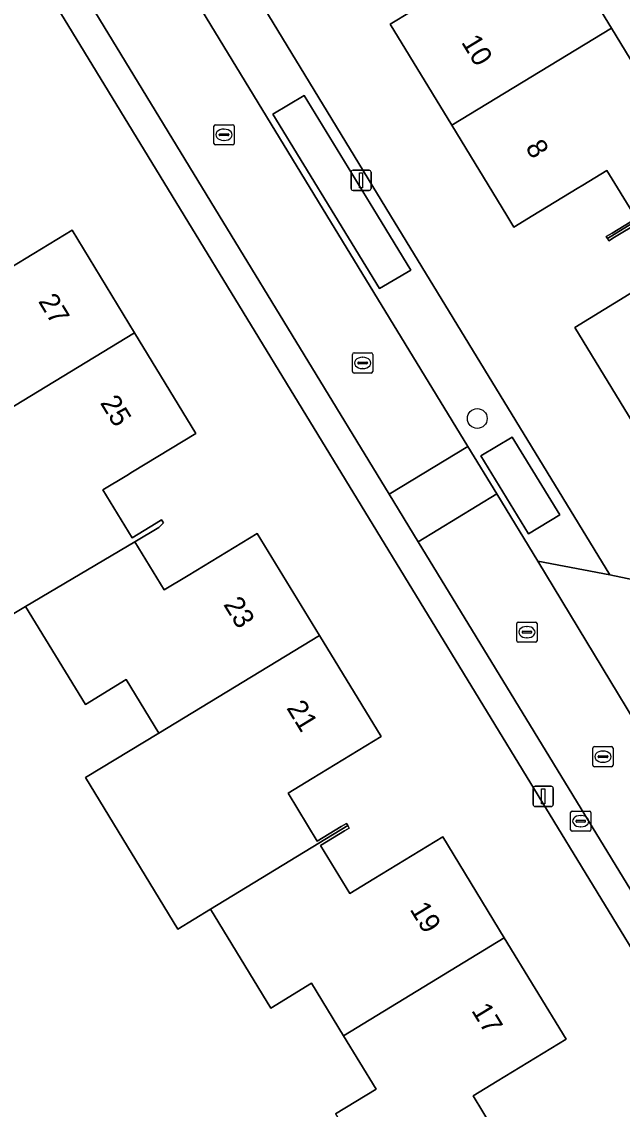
# Model space of a CAD drawing. Extents: x 157767 to 159172, y 387839 to 389425.
# Drawn here: x 158106.2 to 158135.9, y 388455.8 to 388509.6 of the extents above; entities that cross this region are included whole.
import ezdxf

# ---------------------------------------------------------------- set-up
doc = ezdxf.new("R2010")
doc.units = 0
for name, color, linetype in [('IMGEO_Boom', 7, 'Continuous'), ('IMGEO_Brandkraan', 7, 'Continuous'), ('IMGEO_Erf', 7, 'Continuous'), ('IMGEO_Kolk', 7, 'Continuous'), ('IMGEO_Lichtmast', 7, 'Continuous'), ('IMGEO_Pand', 7, 'Continuous'), ('IMGEO_Pand_nummerreeks', 7, 'Continuous'), ('IMGEO_Parkeervlak_open', 7, 'Continuous'), ('IMGEO_Rijbaan_lokaal_open', 7, 'Continuous'), ('IMGEO_Rioolput', 7, 'Continuous'), ('IMGEO_Voetpad_open', 7, 'Continuous')]:
    doc.layers.add(name, color=color, linetype=linetype)

msp = doc.modelspace()

# ---------------------------------------------------------------- linework, layer by layer
at = {"layer": 'IMGEO_Boom'}
msp.add_circle((158128.743, 388489.955), 0.489, dxfattribs=at)
at = {"layer": 'IMGEO_Brandkraan'}
for p, q in [((158133.361, 388469.598), (158133.361, 388470.45)), ((158133.436, 388470.524), (158134.288, 388470.524)), ((158133.62, 388470.018), (158133.62, 388470.03)), ((158133.663, 388470.067), (158134.061, 388470.067)), ((158133.849, 388470.304), (158133.874, 388470.304)), ((158134.104, 388470.03), (158134.104, 388470.018)), ((158134.362, 388470.45), (158134.362, 388469.598)), ((158134.288, 388469.524), (158133.436, 388469.524)), ((158134.058, 388469.981), (158133.66, 388469.981)), ((158133.872, 388469.744), (158133.847, 388469.744))]:
    msp.add_line(p, q, dxfattribs=at)
for points in [[(158133.361, 388469.598), (158133.361, 388470.45)], [(158133.436, 388470.524), (158134.288, 388470.524)], [(158134.362, 388470.45), (158134.362, 388469.598)], [(158134.288, 388469.524), (158133.436, 388469.524)]]:
    msp.add_lwpolyline(points, dxfattribs=at)
for centre, radius, start, end in [((158133.438, 388470.448), 0.0765, 91.552, 178.448), ((158133.438, 388470.448), 0.0765, 91.552, 178.448), ((158133.66, 388470.027), 0.0403, 85.8775, 175.7526), ((158134.065, 388470.029), 0.0386, 1.7309, 96.639), ((158134.286, 388470.448), 0.0765, 1.552, 88.448), ((158134.286, 388470.448), 0.0765, 1.552, 88.448), ((158133.438, 388469.6), 0.0765, 181.552, 268.448), ((158133.438, 388469.6), 0.0765, 181.552, 268.448), ((158133.657, 388470.017), 0.0366, 178.938, 274.7102), ((158134.061, 388470.024), 0.043, 264.8664, 352.4533), ((158134.286, 388469.6), 0.0765, 271.552, 358.448), ((158134.286, 388469.6), 0.0765, 271.552, 358.448)]:
    msp.add_arc(centre, radius, start, end, dxfattribs=at)
for centre, major_axis, ratio, start_param, end_param in [((158133.848, 388470.024), (-0.387, 0.002), 0.722429, 4.712389, 7.853982), ((158133.873, 388470.024), (-0.39, 0.002), 0.717154, 1.570796, 4.712389)]:
    msp.add_ellipse(centre, major_axis=major_axis, ratio=ratio, start_param=start_param, end_param=end_param, dxfattribs=at)
at = {"layer": 'IMGEO_Erf'}
for points in [[(158114.935, 388440.198), (158118.209, 388434.304), (158121.651, 388436.4), (158122.951, 388434.264), (158119.424, 388432.116), (158121.853, 388427.742), (158122.495, 388426.586), (158149.258, 388442.588), (158114.242, 388500), (158071.868, 388569.477)], [(158091.923, 388553.434), (158124.459, 388500), (158135.292, 388482.21), (158138.896, 388481.458), (158169.322, 388500), (158184.058, 388508.98), (158185.047, 388512.009)], [(158133.795, 388511.879), (158135.376, 388509.282), (158136.994, 388506.624)], [(158136.515, 388500), (158135.156, 388502.231), (158133.966, 388501.506), (158133.679, 388501.331), (158131.493, 388500), (158130.552, 388499.427), (158130.203, 388500), (158127.478, 388504.475), (158124.43, 388509.481), (158127.546, 388511.378)], [(158136.723, 388499.647), (158135.538, 388498.925), (158135.251, 388498.75), (158135.178, 388498.87), (158135.125, 388498.957), (158135.413, 388499.132), (158136.602, 388499.857)], [(158105.289, 388497.191), (158108.705, 388499.27), (158111.791, 388494.202), (158114.824, 388489.221), (158111.685, 388487.311), (158111.408, 388487.142), (158110.22, 388486.419), (158111.666, 388484.045), (158112.861, 388484.772), (158113.131, 388484.936), (158113.216, 388484.798), (158112.992, 388484.56), (158111.804, 388483.855), (158113.257, 388481.467), (158114.445, 388482.19), (158117.861, 388484.269), (158120.933, 388479.223), (158123.986, 388474.21), (158120.57, 388472.13), (158119.383, 388471.407), (158120.83, 388469.033), (158122.017, 388469.756), (158122.273, 388469.912), (158122.337, 388469.806), (158122.412, 388469.683), (158122.178, 388469.54), (158120.99, 388468.817), (158122.436, 388466.442), (158123.624, 388467.166), (158127.039, 388469.246), (158130.081, 388464.25), (158133.138, 388459.229), (158129.722, 388457.149), (158128.535, 388456.426), (158129.981, 388454.052)], [(158136.631, 388489.432), (158133.565, 388494.467), (158136.982, 388496.549)], [(158121.732, 388455.537), (158123.737, 388456.758), (158122.126, 388459.404), (158120.544, 388462.002), (158118.527, 388460.774), (158115.546, 388465.67), (158113.932, 388464.687), (158109.368, 388472.181), (158112.994, 388474.389), (158111.385, 388477.031), (158109.358, 388475.796), (158106.404, 388480.648), (158105.408, 388480.057)]]:
    msp.add_lwpolyline(points, dxfattribs=at)
at = {"layer": 'IMGEO_Kolk'}
for p, q in [((158115.79, 388504.498), (158116.642, 388504.498)), ((158115.715, 388503.572), (158115.715, 388504.424)), ((158115.974, 388503.992), (158115.974, 388504.004)), ((158116.412, 388503.955), (158116.014, 388503.955)), ((158116.017, 388504.041), (158116.415, 388504.041)), ((158116.203, 388504.278), (158116.228, 388504.278)), ((158116.458, 388504.004), (158116.458, 388503.992)), ((158116.716, 388504.424), (158116.716, 388503.572)), ((158116.642, 388503.498), (158115.79, 388503.498)), ((158116.226, 388503.718), (158116.201, 388503.718)), ((158122.648, 388493.204), (158123.5, 388493.204)), ((158122.573, 388492.278), (158122.573, 388493.13)), ((158122.832, 388492.698), (158122.832, 388492.71)), ((158123.27, 388492.661), (158122.872, 388492.661)), ((158122.875, 388492.747), (158123.273, 388492.747)), ((158123.061, 388492.984), (158123.086, 388492.984)), ((158123.316, 388492.71), (158123.316, 388492.698)), ((158123.574, 388493.13), (158123.574, 388492.278)), ((158123.5, 388492.204), (158122.648, 388492.204)), ((158123.084, 388492.424), (158123.059, 388492.424)), ((158130.697, 388478.955), (158130.697, 388479.807)), ((158130.772, 388479.881), (158131.624, 388479.881)), ((158131.698, 388479.807), (158131.698, 388478.955)), ((158130.956, 388479.375), (158130.956, 388479.387)), ((158131.394, 388479.338), (158130.996, 388479.338)), ((158130.999, 388479.424), (158131.397, 388479.424)), ((158131.185, 388479.661), (158131.21, 388479.661)), ((158131.44, 388479.387), (158131.44, 388479.375)), ((158131.624, 388478.881), (158130.772, 388478.881)), ((158131.208, 388479.101), (158131.183, 388479.101))]:
    msp.add_line(p, q, dxfattribs=at)
for points in [[(158115.79, 388504.498), (158116.642, 388504.498)], [(158115.715, 388503.572), (158115.715, 388504.424)], [(158116.716, 388504.424), (158116.716, 388503.572)], [(158116.642, 388503.498), (158115.79, 388503.498)], [(158122.648, 388493.204), (158123.5, 388493.204)], [(158122.573, 388492.278), (158122.573, 388493.13)], [(158123.574, 388493.13), (158123.574, 388492.278)], [(158123.5, 388492.204), (158122.648, 388492.204)], [(158130.697, 388478.955), (158130.697, 388479.807)], [(158130.772, 388479.881), (158131.624, 388479.881)], [(158131.698, 388479.807), (158131.698, 388478.955)], [(158131.624, 388478.881), (158130.772, 388478.881)]]:
    msp.add_lwpolyline(points, dxfattribs=at)
for centre, radius, start, end in [((158115.792, 388504.422), 0.0765, 91.552, 178.448), ((158115.792, 388504.422), 0.0765, 91.552, 178.448), ((158116.64, 388504.422), 0.0765, 1.552, 88.448), ((158116.64, 388504.422), 0.0765, 1.552, 88.448), ((158116.014, 388504.001), 0.0403, 85.8775, 175.7526), ((158116.011, 388503.991), 0.0366, 178.938, 274.7102), ((158116.415, 388503.998), 0.043, 264.8664, 352.4533), ((158116.419, 388504.003), 0.0386, 1.7309, 96.639), ((158115.792, 388503.574), 0.0765, 181.552, 268.448), ((158115.792, 388503.574), 0.0765, 181.552, 268.448), ((158116.64, 388503.574), 0.0765, 271.552, 358.448), ((158116.64, 388503.574), 0.0765, 271.552, 358.448), ((158122.65, 388493.128), 0.0765, 91.552, 178.448), ((158122.65, 388493.128), 0.0765, 91.552, 178.448), ((158123.498, 388493.128), 0.0765, 1.552, 88.448), ((158123.498, 388493.128), 0.0765, 1.552, 88.448), ((158122.872, 388492.707), 0.0403, 85.8775, 175.7526), ((158122.869, 388492.697), 0.0366, 178.938, 274.7102), ((158123.273, 388492.704), 0.043, 264.8664, 352.4533), ((158123.277, 388492.709), 0.0386, 1.7309, 96.639), ((158122.65, 388492.28), 0.0765, 181.552, 268.448), ((158122.65, 388492.28), 0.0765, 181.552, 268.448), ((158123.498, 388492.28), 0.0765, 271.552, 358.448), ((158123.498, 388492.28), 0.0765, 271.552, 358.448), ((158130.774, 388479.805), 0.0765, 91.552, 178.448), ((158130.774, 388479.805), 0.0765, 91.552, 178.448), ((158131.622, 388479.805), 0.0765, 1.552, 88.448), ((158131.622, 388479.805), 0.0765, 1.552, 88.448), ((158130.996, 388479.384), 0.0403, 85.8775, 175.7526), ((158130.993, 388479.374), 0.0366, 178.938, 274.7102), ((158131.397, 388479.381), 0.043, 264.8664, 352.4533), ((158131.401, 388479.386), 0.0386, 1.7309, 96.639), ((158130.774, 388478.957), 0.0765, 181.552, 268.448), ((158130.774, 388478.957), 0.0765, 181.552, 268.448), ((158131.622, 388478.957), 0.0765, 271.552, 358.448), ((158131.622, 388478.957), 0.0765, 271.552, 358.448)]:
    msp.add_arc(centre, radius, start, end, dxfattribs=at)
for centre, major_axis, ratio, start_param, end_param in [((158116.202, 388503.998), (-0.387, 0.002), 0.722429, 4.712389, 7.853982), ((158116.227, 388503.998), (-0.39, 0.002), 0.717154, 1.570796, 4.712389), ((158123.06, 388492.704), (-0.387, 0.002), 0.722429, 4.712389, 7.853982), ((158123.085, 388492.704), (-0.39, 0.002), 0.717154, 1.570796, 4.712389), ((158131.184, 388479.381), (-0.387, 0.002), 0.722429, 4.712389, 7.853982), ((158131.209, 388479.381), (-0.39, 0.002), 0.717154, 1.570796, 4.712389)]:
    msp.add_ellipse(centre, major_axis=major_axis, ratio=ratio, start_param=start_param, end_param=end_param, dxfattribs=at)
at = {"layer": 'IMGEO_Lichtmast'}
for p, q in [((158122.5, 388501.345), (158122.5, 388502.145)), ((158122.5, 388502.145), (158122.5, 388501.345)), ((158122.6, 388502.245), (158123.39, 388502.245)), ((158123.39, 388502.245), (158122.6, 388502.245)), ((158123.49, 388502.145), (158123.49, 388501.345)), ((158123.49, 388501.345), (158123.49, 388502.145)), ((158123.39, 388501.245), (158122.6, 388501.245)), ((158122.6, 388501.245), (158123.39, 388501.245)), ((158131.507, 388470.85), (158131.507, 388471.65)), ((158131.507, 388471.65), (158131.507, 388470.85)), ((158131.607, 388471.75), (158132.397, 388471.75)), ((158132.397, 388471.75), (158131.607, 388471.75)), ((158132.497, 388471.65), (158132.497, 388470.85)), ((158132.497, 388470.85), (158132.497, 388471.65)), ((158132.397, 388470.75), (158131.607, 388470.75)), ((158131.607, 388470.75), (158132.397, 388470.75))]:
    msp.add_line(p, q, dxfattribs=at)
for points in [[(158122.92, 388502.12), (158123.07, 388502.12), (158123.07, 388501.37), (158122.92, 388501.37), (158122.92, 388502.12)], [(158131.927, 388471.625), (158132.077, 388471.625), (158132.077, 388470.875), (158131.927, 388470.875), (158131.927, 388471.625)]]:
    msp.add_lwpolyline(points, dxfattribs=at)
for centre, start, end in [((158122.6, 388502.145), 90, 180), ((158122.6, 388502.145), 90, 180), ((158123.39, 388502.145), 0, 90), ((158123.39, 388502.145), 360, 90), ((158122.6, 388501.345), 180, 270), ((158122.6, 388501.345), 180, 270), ((158123.39, 388501.345), 270, 0), ((158123.39, 388501.345), 270, 0), ((158131.607, 388471.65), 90, 180), ((158131.607, 388471.65), 90, 180), ((158132.397, 388471.65), 0, 90), ((158132.397, 388471.65), 360, 90), ((158131.607, 388470.85), 180, 270), ((158131.607, 388470.85), 180, 270), ((158132.397, 388470.85), 270, 0), ((158132.397, 388470.85), 270, 0)]:
    msp.add_arc(centre, 0.1, start, end, dxfattribs=at)
at = {"layer": 'IMGEO_Pand'}
for points in [[(158127.478, 388504.475), (158135.376, 388509.282), (158133.795, 388511.879), (158135.832, 388513.119), (158132.817, 388518.071), (158126.035, 388513.86), (158127.546, 388511.378), (158124.43, 388509.481)], [(158135.178, 388498.87), (158137.035, 388500), (158141.986, 388503.013), (158139.032, 388507.865), (158136.994, 388506.624), (158135.376, 388509.282), (158127.478, 388504.475), (158130.203, 388500), (158130.552, 388499.427), (158131.493, 388500), (158133.679, 388501.331), (158133.966, 388501.506), (158135.156, 388502.231), (158136.515, 388500), (158136.602, 388499.857), (158135.413, 388499.132), (158135.125, 388498.957)], [(158135.178, 388498.87), (158135.251, 388498.75), (158135.538, 388498.925), (158136.723, 388499.647), (158138.169, 388497.272), (158136.982, 388496.549), (158133.565, 388494.467), (158136.631, 388489.432), (158144.521, 388494.275), (158142.95, 388496.855), (158144.982, 388498.092), (158143.82, 388500), (158141.986, 388503.013), (158137.035, 388500)], [(158111.791, 388494.202), (158108.705, 388499.27), (158105.289, 388497.191), (158104.101, 388496.468), (158102.708, 388498.758), (158103.896, 388499.481), (158104.111, 388499.612), (158103.967, 388499.848), (158097.207, 388495.732), (158100.219, 388490.785), (158102.249, 388492.021), (158103.862, 388489.373)], [(158110.22, 388486.419), (158111.408, 388487.142), (158111.685, 388487.311), (158114.824, 388489.221), (158111.791, 388494.202), (158103.862, 388489.373), (158100.935, 388487.59), (158105.408, 388480.057), (158106.404, 388480.648), (158111.804, 388483.855), (158112.992, 388484.56), (158113.216, 388484.798), (158113.131, 388484.936), (158112.861, 388484.772), (158111.666, 388484.045)], [(158117.861, 388484.269), (158114.445, 388482.19), (158113.257, 388481.467), (158111.804, 388483.855), (158106.404, 388480.648), (158109.358, 388475.796), (158111.385, 388477.031), (158112.994, 388474.389), (158120.933, 388479.223)], [(158120.57, 388472.13), (158123.986, 388474.21), (158120.933, 388479.223), (158112.994, 388474.389), (158109.368, 388472.181), (158113.932, 388464.687), (158115.546, 388465.67), (158122.337, 388469.806), (158122.273, 388469.912), (158122.017, 388469.756), (158120.83, 388469.033), (158119.383, 388471.407)], [(158122.126, 388459.404), (158130.081, 388464.25), (158127.039, 388469.246), (158123.624, 388467.166), (158122.436, 388466.442), (158120.99, 388468.817), (158122.178, 388469.54), (158122.412, 388469.683), (158122.337, 388469.806), (158115.546, 388465.67), (158118.527, 388460.774), (158120.544, 388462.002)], [(158124.684, 388450.689), (158131.497, 388454.838), (158131.436, 388454.938), (158131.168, 388454.775), (158129.981, 388454.052), (158128.535, 388456.426), (158129.722, 388457.149), (158133.138, 388459.229), (158130.081, 388464.25), (158122.126, 388459.404), (158123.737, 388456.758), (158121.732, 388455.537)]]:
    msp.add_lwpolyline(points, close=True, dxfattribs=at)
at = {"layer": 'IMGEO_Parkeervlak_open'}
for points in [[(158123.905, 388496.389), (158125.451, 388497.297), (158123.803, 388500), (158120.179, 388505.946), (158118.631, 388505.017), (158121.698, 388500)], [(158131.272, 388484.244), (158132.823, 388485.188), (158130.476, 388489.038), (158128.925, 388488.108)]]:
    msp.add_lwpolyline(points, close=True, dxfattribs=at)
at = {"layer": 'IMGEO_Rijbaan_lokaal_open'}
for points in [[(158097.602, 388530.139), (158115.979, 388500), (158124.39, 388486.206), (158128.272, 388488.572), (158121.307, 388500), (158101.494, 388532.512)], [(158163.433, 388488.09), (158161.098, 388491.933), (158142.664, 388480.74), (158138.896, 388481.458), (158135.292, 388482.21), (158131.734, 388482.891), (158140.095, 388469.071), (158141.163, 388472.783), (158141.832, 388474.956)], [(158124.39, 388486.206), (158125.821, 388483.858), (158129.703, 388486.224), (158128.272, 388488.572)], [(158140.095, 388469.071), (158131.734, 388482.891), (158129.703, 388486.224), (158125.821, 388483.858), (158150.494, 388443.392), (158154.35, 388445.722)]]:
    msp.add_lwpolyline(points, close=True, dxfattribs=at)
at = {"layer": 'IMGEO_Rioolput'}
for p, q in [((158134.46, 388472.792), (158134.46, 388473.644)), ((158134.535, 388473.718), (158135.387, 388473.718)), ((158134.762, 388473.261), (158135.16, 388473.261)), ((158134.948, 388473.498), (158134.973, 388473.498)), ((158135.461, 388473.644), (158135.461, 388472.792)), ((158134.719, 388473.212), (158134.719, 388473.224)), ((158135.157, 388473.175), (158134.759, 388473.175)), ((158134.971, 388472.938), (158134.946, 388472.938)), ((158135.203, 388473.224), (158135.203, 388473.212)), ((158135.387, 388472.718), (158134.535, 388472.718))]:
    msp.add_line(p, q, dxfattribs=at)
for points in [[(158134.46, 388472.792), (158134.46, 388473.644)], [(158134.535, 388473.718), (158135.387, 388473.718)], [(158135.461, 388473.644), (158135.461, 388472.792)], [(158135.387, 388472.718), (158134.535, 388472.718)]]:
    msp.add_lwpolyline(points, dxfattribs=at)
for centre, radius, start, end in [((158134.537, 388473.642), 0.0765, 91.552, 178.448), ((158134.537, 388473.642), 0.0765, 91.552, 178.448), ((158134.759, 388473.221), 0.0403, 85.8775, 175.7526), ((158135.164, 388473.223), 0.0386, 1.7309, 96.639), ((158135.385, 388473.642), 0.0765, 1.552, 88.448), ((158135.385, 388473.642), 0.0765, 1.552, 88.448), ((158134.537, 388472.794), 0.0765, 181.552, 268.448), ((158134.537, 388472.794), 0.0765, 181.552, 268.448), ((158134.756, 388473.211), 0.0366, 178.938, 274.7102), ((158135.16, 388473.218), 0.043, 264.8664, 352.4533), ((158135.385, 388472.794), 0.0765, 271.552, 358.448), ((158135.385, 388472.794), 0.0765, 271.552, 358.448)]:
    msp.add_arc(centre, radius, start, end, dxfattribs=at)
for centre, major_axis, ratio, start_param, end_param in [((158134.947, 388473.218), (-0.387, 0.002), 0.722429, 4.712389, 7.853982), ((158134.972, 388473.218), (-0.39, 0.002), 0.717154, 1.570796, 4.712389)]:
    msp.add_ellipse(centre, major_axis=major_axis, ratio=ratio, start_param=start_param, end_param=end_param, dxfattribs=at)
at = {"layer": 'IMGEO_Voetpad_open'}
msp.add_lwpolyline([(158071.868, 388569.477), (158114.242, 388500), (158149.258, 388442.588), (158149.402, 388442.676), (158150.899, 388440.222), (158151.9, 388440.83), (158150.371, 388443.318), (158150.494, 388443.392), (158125.821, 388483.858), (158124.39, 388486.206), (158115.979, 388500), (158097.602, 388530.139), (158096.176, 388532.478), (158094.733, 388534.845), (158084.853, 388551.014), (158078.779, 388560.955), (158097.656, 388572.467), (158106.093, 388600.404), (158106.836, 388602.865), (158112.707, 388622.305)], dxfattribs=at)
for points in [[(158091.923, 388553.434), (158088.768, 388553.399), (158097.342, 388539.257), (158097.907, 388538.397), (158100.068, 388534.851), (158101.494, 388532.512), (158121.307, 388500), (158128.272, 388488.572), (158129.703, 388486.224), (158131.734, 388482.891), (158135.292, 388482.21), (158124.459, 388500)], [(158120.179, 388505.946), (158123.803, 388500), (158125.451, 388497.297), (158123.905, 388496.389), (158121.698, 388500), (158118.631, 388505.017)], [(158130.476, 388489.038), (158132.823, 388485.188), (158131.272, 388484.244), (158128.925, 388488.108)]]:
    msp.add_lwpolyline(points, close=True, dxfattribs=at)

# ---------------------------------------------------------------- texts
at = {"layer": 'IMGEO_Pand_nummerreeks'}
for s, rotation, p in [('10', 301.3373, (158127.928, 388508.581)), ('8', 301.3373, (158131.098, 388503.375)), ('27', 301.3379, (158107.004, 388495.758)), ('25', 301.3406, (158110.064, 388490.733)), ('23', 301.3349, (158116.162, 388480.754)), ('21', 301.3349, (158119.283, 388475.629)), ('19', 301.3358, (158125.38, 388465.664)), ('17', 301.3358, (158128.429, 388460.655))]:
    msp.add_text(s, height=1, rotation=rotation, dxfattribs=at).set_placement(p)

doc.saveas('drawing.dxf')
